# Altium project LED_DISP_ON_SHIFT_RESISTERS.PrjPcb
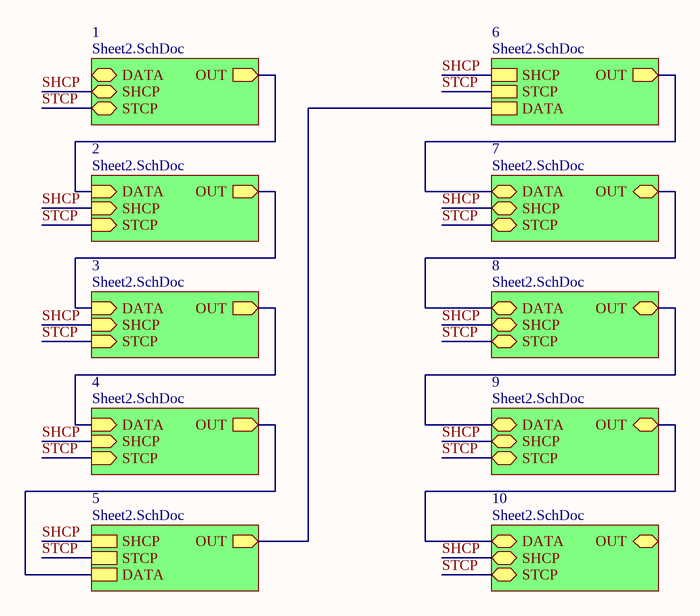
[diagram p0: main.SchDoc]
2 sheets, 100 parts. Net scope: hierarchical (ports join the sheet entries above them; power ports are global).
Board file: PCB1.PcbDoc
Sheets:
  main.SchDoc
    1 = Sheet2.SchDoc
    2 = Sheet2.SchDoc
    3 = Sheet2.SchDoc
    4 = Sheet2.SchDoc
    5 = Sheet2.SchDoc
    6 = Sheet2.SchDoc
    7 = Sheet2.SchDoc
    8 = Sheet2.SchDoc
    9 = Sheet2.SchDoc
    10 = Sheet2.SchDoc

## Sheet main.SchDoc
size A

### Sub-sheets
1 = Sheet2.SchDoc: DATA, SHCP, STCP, OUT (out)
2 = Sheet2.SchDoc: DATA (in), SHCP (in), STCP (in), OUT (out)
3 = Sheet2.SchDoc: DATA (in), SHCP (in), STCP (in), OUT (out)
4 = Sheet2.SchDoc: DATA (in), SHCP (in), STCP (in), OUT (out)
5 = Sheet2.SchDoc: SHCP, STCP, DATA, OUT (out)
6 = Sheet2.SchDoc: SHCP, STCP, DATA, OUT (out)
7 = Sheet2.SchDoc: DATA, SHCP, STCP, OUT
8 = Sheet2.SchDoc: DATA, SHCP, STCP, OUT
9 = Sheet2.SchDoc: DATA, SHCP, STCP, OUT
10 = Sheet2.SchDoc: DATA, SHCP, STCP, OUT

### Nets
SHCP: sheet 1/SHCP, sheet 2/SHCP, sheet 3/SHCP, sheet 4/SHCP, sheet 5/SHCP, sheet 6/SHCP, sheet 7/SHCP, sheet 8/SHCP, sheet 9/SHCP, sheet 10/SHCP
STCP: sheet 1/STCP, sheet 2/STCP, sheet 3/STCP, sheet 4/STCP, sheet 5/STCP, sheet 6/STCP, sheet 7/STCP, sheet 8/STCP, sheet 9/STCP, sheet 10/STCP
NetU1_1_9: sheet 1/OUT, sheet 2/DATA
NetU1_2_9: sheet 2/OUT, sheet 3/DATA
NetU1_3_9: sheet 3/OUT, sheet 4/DATA
NetU1_4_9: sheet 4/OUT, sheet 5/DATA
NetU1_5_9: sheet 5/OUT, sheet 6/DATA
NetU1_6_9: sheet 6/OUT, sheet 7/DATA
NetU1_7_9: sheet 7/OUT, sheet 8/DATA
NetU1_8_9: sheet 8/OUT, sheet 9/DATA
NetU1_9_9: sheet 9/OUT, sheet 10/DATA

## Sheet Sheet2.SchDoc
size A
Used 10 times, as channels 1, 2, 3, 4, 5, 6, 7, 8, 9, 10. Parts and nets are listed once, with the designators drawn on the sheet.
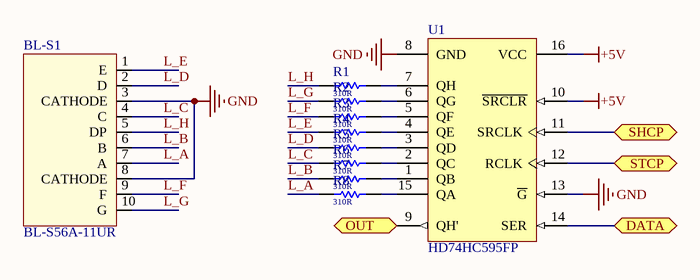
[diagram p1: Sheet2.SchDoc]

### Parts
BL-S1  BL-S56A-11UR  [BL-S56A-11UR]
R1  310R  [Res0805]
R2  310R  [Res0805]
R3  310R  [Res0805]
R4  310R  [Res0805]
R5  310R  [Res0805]
R6  310R  [Res0805]
R7  310R  [Res0805]
R8  310R  [Res0805]
U1  HD74HC595FP  [PRSP0016DH-B_N]

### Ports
DATA, OUT (out), SHCP, STCP

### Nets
+5V: U1.10(~{SRCLR}) U1.16(VCC)
GND: BL-S1.3(CATHODE) BL-S1.8(CATHODE) U1.8(GND) U1.13(~{G})
DATA: U1.14(SER) ; port DATA
L_A: BL-S1.7(A) R8.1
L_B: BL-S1.6(B) R7.1
L_C: BL-S1.4(C) R6.1
L_D: BL-S1.2(D) R5.1
L_E: BL-S1.1(E) R4.1
L_F: BL-S1.9(F) R3.1
L_G: BL-S1.10(G) R2.1
L_H: BL-S1.5(DP) R1.1
OUT: U1.9(QH') ; port OUT
SHCP: U1.11(SRCLK) ; port SHCP
STCP: U1.12(RCLK) ; port STCP
NetR1_2: R1.2 U1.7(QH)
NetR2_2: R2.2 U1.6(QG)
NetR3_2: R3.2 U1.5(QF)
NetR4_2: R4.2 U1.4(QE)
NetR5_2: R5.2 U1.3(QD)
NetR6_2: R6.2 U1.2(QC)
NetR7_2: R7.2 U1.1(QB)
NetR8_2: R8.2 U1.15(QA)

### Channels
1: designators end in _1; ports DATA=NetU1_1_14 OUT=NetU1_1_9 SHCP=SHCP STCP=STCP
2: designators end in _2; ports DATA=NetU1_1_9 OUT=NetU1_2_9 SHCP=SHCP STCP=STCP
3: designators end in _3; ports DATA=NetU1_2_9 OUT=NetU1_3_9 SHCP=SHCP STCP=STCP
4: designators end in _4; ports DATA=NetU1_3_9 OUT=NetU1_4_9 SHCP=SHCP STCP=STCP
5: designators end in _5; ports DATA=NetU1_4_9 OUT=NetU1_5_9 SHCP=SHCP STCP=STCP
6: designators end in _6; ports DATA=NetU1_5_9 OUT=NetU1_6_9 SHCP=SHCP STCP=STCP
7: designators end in _7; ports DATA=NetU1_6_9 OUT=NetU1_7_9 SHCP=SHCP STCP=STCP
8: designators end in _8; ports DATA=NetU1_7_9 OUT=NetU1_8_9 SHCP=SHCP STCP=STCP
9: designators end in _9; ports DATA=NetU1_8_9 OUT=NetU1_9_9 SHCP=SHCP STCP=STCP
10: designators end in _10; ports DATA=NetU1_9_9 OUT=NetU1_10_9 SHCP=SHCP STCP=STCP

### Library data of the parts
BL-S1 = Component_1
R1-R8 = Res1: Resistor
U1 = HD74HC595FP: 8-bit Shift Register / Latch with 3-State Outputs

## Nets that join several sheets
+5V: 1 (U1_1.10 U1_1.16), 2 (U1_2.10 U1_2.16), 3 (U1_3.10 U1_3.16), 4 (U1_4.10 U1_4.16), 5 (U1_5.10 U1_5.16), 6 (U1_6.10 U1_6.16), 7 (U1_7.10 U1_7.16), 8 (U1_8.10 U1_8.16), 9 (U1_9.10 U1_9.16), 10 (U1_10.10 U1_10.16)
GND: 1 (BL-S1_1.3 BL-S1_1.8 U1_1.8 U1_1.13), 2 (BL-S1_2.3 BL-S1_2.8 U1_2.8 U1_2.13), 3 (BL-S1_3.3 BL-S1_3.8 U1_3.8 U1_3.13), 4 (BL-S1_4.3 BL-S1_4.8 U1_4.8 U1_4.13), 5 (BL-S1_5.3 BL-S1_5.8 U1_5.8 U1_5.13), 6 (BL-S1_6.3 BL-S1_6.8 U1_6.8 U1_6.13), 7 (BL-S1_7.3 BL-S1_7.8 U1_7.8 U1_7.13), 8 (BL-S1_8.3 BL-S1_8.8 U1_8.8 U1_8.13), 9 (BL-S1_9.3 BL-S1_9.8 U1_9.8 U1_9.13), 10 (BL-S1_10.3 BL-S1_10.8 U1_10.8 U1_10.13)
NetU1_1_9: 1 (U1_1.9), 2 (U1_2.14)
NetU1_2_9: 2 (U1_2.9), 3 (U1_3.14)
NetU1_3_9: 3 (U1_3.9), 4 (U1_4.14)
NetU1_4_9: 4 (U1_4.9), 5 (U1_5.14)
NetU1_5_9: 5 (U1_5.9), 6 (U1_6.14)
NetU1_6_9: 6 (U1_6.9), 7 (U1_7.14)
NetU1_7_9: 7 (U1_7.9), 8 (U1_8.14)
NetU1_8_9: 8 (U1_8.9), 9 (U1_9.14)
NetU1_9_9: 9 (U1_9.9), 10 (U1_10.14)
SHCP: 1 (U1_1.11), 2 (U1_2.11), 3 (U1_3.11), 4 (U1_4.11), 5 (U1_5.11), 6 (U1_6.11), 7 (U1_7.11), 8 (U1_8.11), 9 (U1_9.11), 10 (U1_10.11)
STCP: 1 (U1_1.12), 2 (U1_2.12), 3 (U1_3.12), 4 (U1_4.12), 5 (U1_5.12), 6 (U1_6.12), 7 (U1_7.12), 8 (U1_8.12), 9 (U1_9.12), 10 (U1_10.12)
